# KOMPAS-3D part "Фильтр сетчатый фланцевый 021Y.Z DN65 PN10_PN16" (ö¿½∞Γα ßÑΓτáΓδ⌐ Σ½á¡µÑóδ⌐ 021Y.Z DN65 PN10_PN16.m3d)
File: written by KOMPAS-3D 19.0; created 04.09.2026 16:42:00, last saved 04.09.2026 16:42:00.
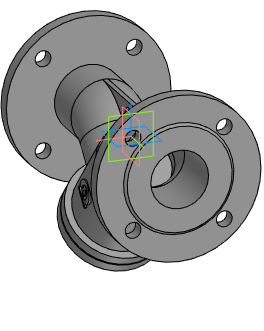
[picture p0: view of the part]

Document properties: Автор: Энергия; Полное имя файла: Z:\3.Личные\sachek\Dendor\_3D для проектировщиков\8.1 Фильтр сетчатый 021Y.Z\021Y.Z_STP\Фильтр сетчатый фланцевый 021Y.Z DN65 PN10_PN16.m3d

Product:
- Part/product: Фильтр сетчатый фланцевый 021Y.Z DN65 PN10_PN16

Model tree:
1. Операция без истории:1  (labels: Фильтр сетчатый фланцевый 021Y.Z DN65 PN10_PN16)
